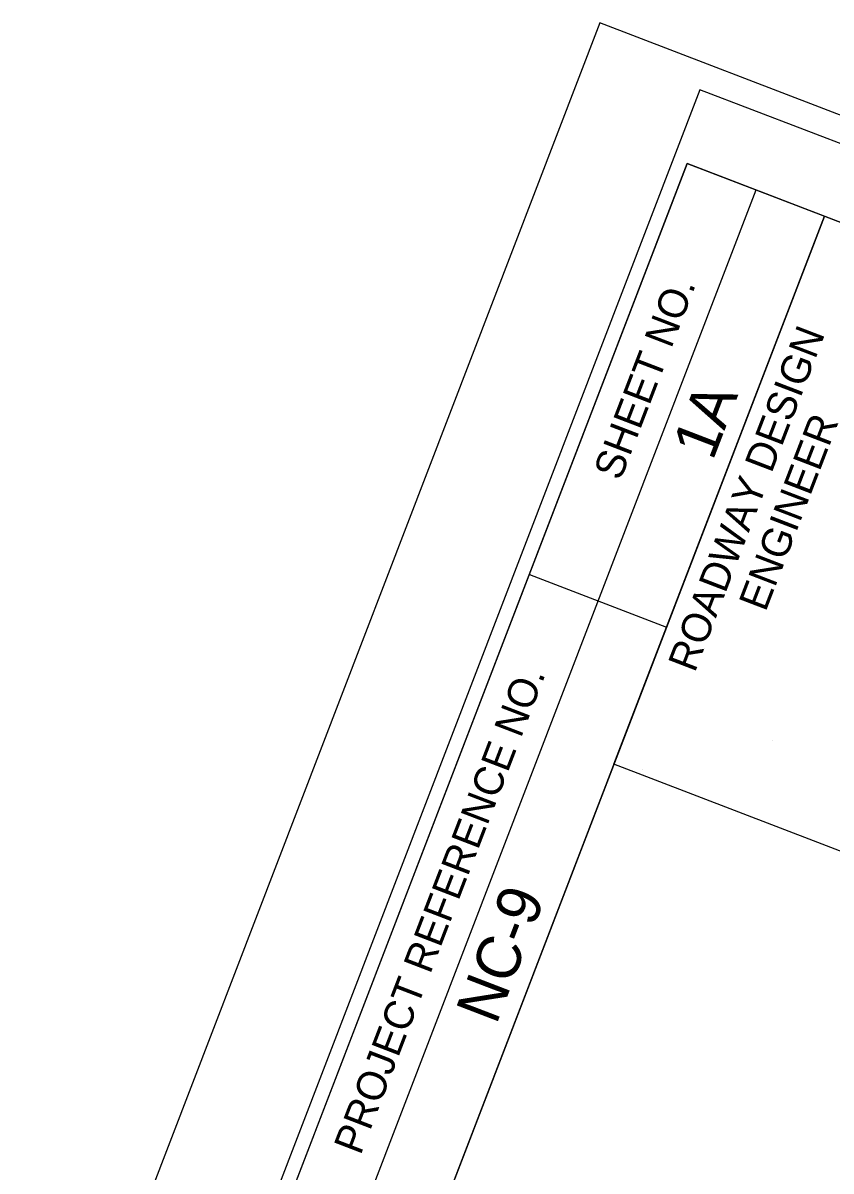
# Model space of a CAD drawing. Extents: x 1015221 to 1064345, y 619216 to 647967.
# Drawn here: x 1033081 to 1034182, y 641092 to 642657 of the extents above; entities that cross this region are included whole.
import ezdxf

# ---------------------------------------------------------------- set-up
doc = ezdxf.new("R2010")
doc.units = 0
for name, color, linetype in [('Scratch_Level_0', 7, 'Continuous'), ('Sheet Cutting Line CELL', 7, 'Continuous'), ('Sheet Data Field CELL', 7, 'Continuous'), ('Sheet Plan CELL', 7, 'Continuous'), ('Sheet Plot Border Inside CELL', 7, 'Continuous'), ('Sheet Plot Border Outside CELL', 7, 'Continuous')]:
    doc.layers.add(name, color=color, linetype=linetype)

msp = doc.modelspace()

# ---------------------------------------------------------------- linework, layer by layer
at = {"layer": 'Scratch_Level_0'}
for p, q in [((1034102.5, 641679), (1034102.5, 641679)), ((1033925.3, 641639), (1033925.3, 641639))]:
    msp.add_line(p, q, dxfattribs=at)
at = {"layer": 'Sheet Cutting Line CELL'}
msp.add_line((1033866.8, 642657.3), (1029036.6, 630085.3), dxfattribs=at)
at = {"layer": 'Sheet Plan CELL'}
for p, q in [((1033505.8, 640935.9), (1034079.8, 642429.8)), ((1033599.1, 640900), (1034173.1, 642394)), ((1033599.1, 640900), (1034173.1, 642394)), ((1033771.2, 641905.6), (1033957.9, 641833.9))]:
    msp.add_line(p, q, dxfattribs=at)
for points in [[(1033986, 642465.8), (1029682.3, 631264.1), (1037523.5, 628251.5), (1041827.2, 639453.2)], [(1033412.1, 640971.9), (1033986, 642465.8), (1034173.1, 642394), (1033599.1, 640900)], [(1033886.1, 641646.8), (1034173.1, 642394), (1035013.3, 642071.2), (1034726.1, 641324.2)]]:
    msp.add_lwpolyline(points, close=True, dxfattribs=at)
at = {"layer": 'Sheet Plot Border Inside CELL'}
msp.add_lwpolyline([(1037101.7, 627098), (1041881.8, 639539.4), (1034003.2, 642566.3), (1029223.2, 630125)], close=True, dxfattribs=at)
at = {"layer": 'Sheet Plot Border Outside CELL'}
msp.add_lwpolyline([(1037213.8, 626943.6), (1042044, 639515.6), (1033866.8, 642657.3), (1029036.6, 630085.3)], close=True, dxfattribs=at)

# ---------------------------------------------------------------- texts
at = {"layer": 'Sheet Data Field CELL'}
for s, p in [('1A ', (1034020.6, 642059.3)), ('NC-9', (1033725.6, 641290.4))]:
    msp.add_text(s, height=60, rotation=68.983, dxfattribs=at).set_placement(p)
at = {"layer": 'Sheet Plan CELL'}
for s, height, rotation, p in [('SHEET NO.', 40, 68.983, (1033894.8, 642032.1)), ('ROADWAY DESIGN', 40.001, 68.9841, (1033996.2, 641770.5)), ('ENGINEER', 40, 68.9841, (1034092.6, 641853.4)), ('PROJECT REFERENCE NO.', 40.001, 68.983, (1033540.7, 641112.7))]:
    msp.add_text(s, height=height, rotation=rotation, dxfattribs=at).set_placement(p)

doc.saveas('drawing.dxf')
